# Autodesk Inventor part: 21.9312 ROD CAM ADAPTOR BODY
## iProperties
Created: 2007-03
Part Number: 21.9312 ROD CAM ADAPTOR BODY
Document SubType Name: Modeling
Designer: Andy Moles
Material: Steel
Mass: 27.9312 g
Surface Area: 23.9033 cm^2
Volume: 3.55812 cm^3
Density: 7.85 g/cm^3
Author: Andy Moles
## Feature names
1. Base1
